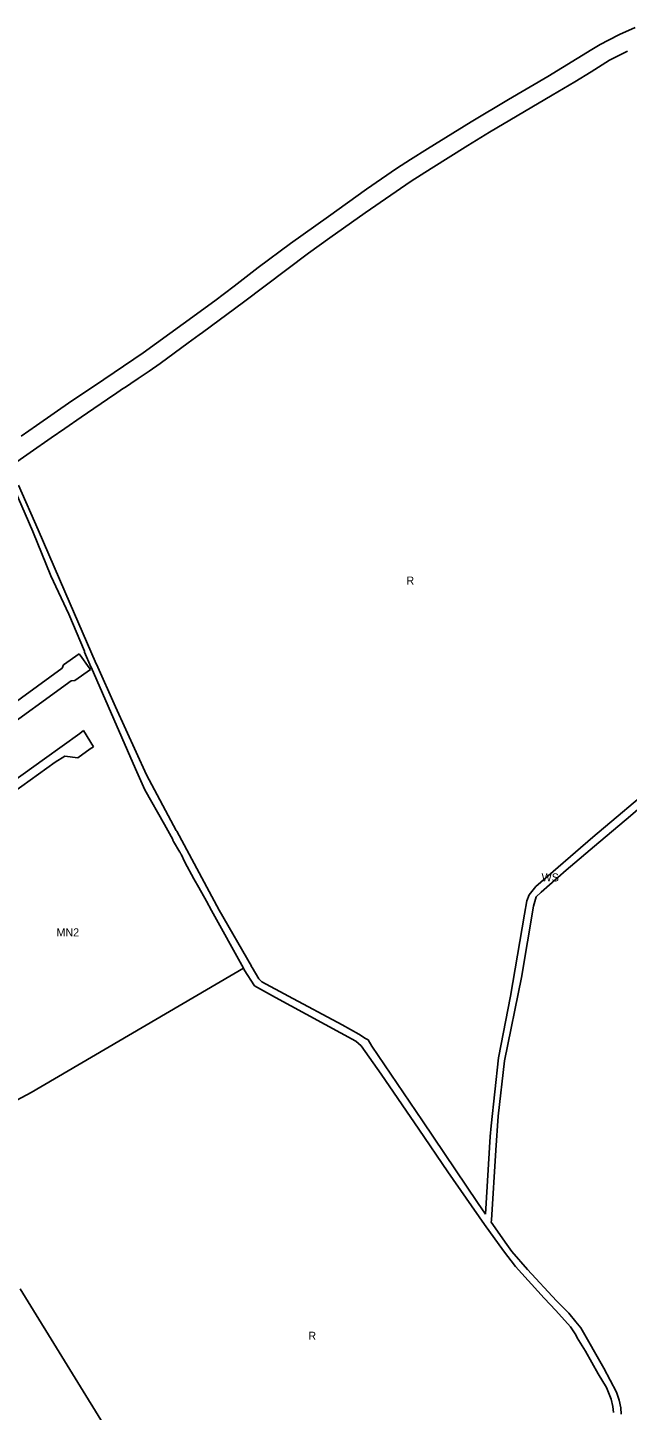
# Model space of a CAD drawing. Extents: x 7435758 to 7439981, y 5550649 to 5554049.
# Drawn here: x 7437849 to 7438238, y 5551345 to 5552243 of the extents above; entities that cross this region are included whole.
import ezdxf

# ---------------------------------------------------------------- set-up
doc = ezdxf.new("R2010")
doc.units = 0
doc.layers.add('linie_rozgraniczające', color=7, linetype='Continuous')
doc.layers.add('oznaczenia_przeznaczen', color=7, linetype='Continuous')

msp = doc.modelspace()

# ---------------------------------------------------------------- linework, layer by layer
at = {"layer": 'linie_rozgraniczające'}
for p, q in [((7438233.29, 5552238.74), (7438226.09, 5552235.07)), ((7438243.46, 5552243.15), (7438233.29, 5552238.74)), ((7438220.7, 5552232.29), (7438215.4, 5552228.93)), ((7438226.09, 5552235.07), (7438220.7, 5552232.29)), ((7438215.4, 5552228.93), (7438186.88, 5552211.52)), ((7438214.95, 5552214.44), (7438226.89, 5552222)), ((7438226.89, 5552222), (7438238.58, 5552227.97)), ((7438186.88, 5552211.52), (7438161.26, 5552196.44)), ((7438204.39, 5552207.89), (7438214.95, 5552214.44)), ((7438189.7, 5552199.25), (7438204.39, 5552207.89)), ((7438161.26, 5552196.44), (7438136.96, 5552182.06)), ((7438148.96, 5552175.27), (7438189.7, 5552199.25)), ((7438136.96, 5552182.06), (7438108.66, 5552164.34)), ((7438111.07, 5552151.69), (7438134.87, 5552166.6)), ((7438134.87, 5552166.6), (7438148.96, 5552175.27)), ((7438097.62, 5552157.42), (7438088.61, 5552151.62)), ((7438108.66, 5552164.34), (7438097.62, 5552157.42)), ((7438088.61, 5552151.62), (7438069.13, 5552138.13)), ((7438098, 5552143.5), (7438111.07, 5552151.69)), ((7438068.22, 5552122.79), (7438098, 5552143.5)), ((7438069.13, 5552138.13), (7438044.29, 5552120.56)), ((7438045.32, 5552106.59), (7438068.22, 5552122.79)), ((7438044.29, 5552120.56), (7438019.76, 5552103)), ((7438031.31, 5552096.54), (7438045.32, 5552106.59)), ((7437989.26, 5552064.78), (7438031.31, 5552096.54)), ((7438019.76, 5552103), (7437998.76, 5552087.24)), ((7437998.76, 5552087.24), (7437983.05, 5552075.14)), ((7437983.05, 5552075.14), (7437970.58, 5552065.72)), ((7437970.58, 5552065.72), (7437949.92, 5552050.67)), ((7437962.53, 5552045.04), (7437989.26, 5552064.78)), ((7437949.92, 5552050.67), (7437924.09, 5552031.87)), ((7437953.31, 5552038.3), (7437960.46, 5552043.5)), ((7437960.46, 5552043.51), (7437962.53, 5552045.04)), ((7437960.46, 5552043.5), (7437960.46, 5552043.51)), ((7437924.09, 5552031.87), (7437892.36, 5552010.52)), ((7437935.04, 5552024.99), (7437953.31, 5552038.3)), ((7437927.96, 5552020.01), (7437935.04, 5552024.99)), ((7437915.95, 5552011.93), (7437920.87, 5552015.23)), ((7437920.87, 5552015.23), (7437927.96, 5552020.01)), ((7437892.36, 5552010.52), (7437877.64, 5552000.61)), ((7437883.68, 5551990.07), (7437905.05, 5552004.59)), ((7437905.05, 5552004.59), (7437905.45, 5552004.86)), ((7437905.45, 5552004.86), (7437906.93, 5552005.82)), ((7437906.93, 5552005.82), (7437911.34, 5552008.83)), ((7437911.34, 5552008.83), (7437911.36, 5552008.84)), ((7437911.36, 5552008.84), (7437911.95, 5552009.24)), ((7437911.95, 5552009.24), (7437915.95, 5552011.93)), ((7437877.64, 5552000.61), (7437854.78, 5551984.69)), ((7437873.1, 5551982.72), (7437883.68, 5551990.07)), ((7437854.78, 5551984.69), (7437844.78, 5551977.68)), ((7437864.27, 5551976.69), (7437873.1, 5551982.72)), ((7437850.63, 5551967.13), (7437864.27, 5551976.69)), ((7437834.89, 5551956.1), (7437850.63, 5551967.13)), ((7437840.36, 5551943.66), (7437852.28, 5551915.86)), ((7437855.94, 5551916.89), (7437843.13, 5551945.94)), ((7437852.28, 5551915.86), (7437864.12, 5551887.06)), ((7437873.07, 5551876.82), (7437855.94, 5551916.89)), ((7437864.12, 5551887.06), (7437875.74, 5551862.03)), ((7437893.59, 5551829.8), (7437873.07, 5551876.82)), ((7437875.74, 5551862.03), (7437885.84, 5551837.94)), ((7437872.36, 5551829.12), (7437882.54, 5551836.36)), ((7437882.54, 5551836.36), (7437883.17, 5551835.49)), ((7437883.17, 5551835.49), (7437889.03, 5551827.25)), ((7437885.84, 5551837.94), (7437885.85, 5551837.43)), ((7437885.85, 5551837.43), (7437889.97, 5551827.94)), ((7437807.11, 5551780.31), (7437871.35, 5551826.92)), ((7437871.35, 5551826.92), (7437872.36, 5551829.12)), ((7437889.79, 5551826.18), (7437879.61, 5551818.93)), ((7437889.03, 5551827.25), (7437889.79, 5551826.18)), ((7437889.97, 5551827.94), (7437890.35, 5551827.58)), ((7437890.35, 5551827.58), (7437905.06, 5551793.87)), ((7437893.52, 5551829.77), (7437893.59, 5551829.8)), ((7437893.73, 5551829.5), (7437893.52, 5551829.77)), ((7437906.03, 5551801.93), (7437893.73, 5551829.5)), ((7437877.2, 5551818.71), (7437812.75, 5551772.12)), ((7437879.61, 5551818.93), (7437877.2, 5551818.71)), ((7437926.23, 5551757.79), (7437906.03, 5551801.93)), ((7437905.06, 5551793.87), (7437918.96, 5551761.62)), ((7437860.01, 5551768.18), (7437882.93, 5551784.61)), ((7437882.93, 5551784.61), (7437885.38, 5551786.59)), ((7437885.38, 5551786.59), (7437891.82, 5551775.94)), ((7437889.51, 5551774.56), (7437881.54, 5551768.85)), ((7437891.82, 5551775.94), (7437889.51, 5551774.56)), ((7438237.71, 5551728.66), (7438294.16, 5551777.35)), ((7437866.87, 5551766.02), (7437819.07, 5551731.54)), ((7437832.18, 5551748.17), (7437860.01, 5551768.18)), ((7437873.16, 5551769.78), (7437866.87, 5551766.02)), ((7437881.54, 5551768.85), (7437873.16, 5551769.78)), ((7438271.71, 5551764.41), (7438215.92, 5551717.18)), ((7437918.96, 5551761.62), (7437925.15, 5551748.04)), ((7437945.52, 5551721.51), (7437926.23, 5551757.79)), ((7437925.15, 5551748.04), (7437937.86, 5551725.48)), ((7438219.83, 5551713.75), (7438237.71, 5551728.66)), ((7437937.86, 5551725.48), (7437943.28, 5551715.71)), ((7437945.97, 5551721.06), (7437945.52, 5551721.51)), ((7437973.32, 5551669.86), (7437945.97, 5551721.06)), ((7438215.92, 5551717.18), (7438178.9, 5551685.08)), ((7437943.28, 5551715.71), (7437943.28, 5551715.19)), ((7437943.28, 5551715.19), (7437943.33, 5551715.23)), ((7437943.33, 5551715.23), (7437943.81, 5551714.42)), ((7437943.81, 5551714.42), (7437947.91, 5551707.42)), ((7438198.66, 5551695.84), (7438219.83, 5551713.75)), ((7437947.91, 5551707.42), (7437948.02, 5551707.38)), ((7437948.02, 5551707.38), (7437948.37, 5551706.64)), ((7437948.37, 5551706.64), (7437948.69, 5551706.09)), ((7437948.69, 5551706.09), (7437948.64, 5551706.06)), ((7437948.64, 5551706.06), (7437951.04, 5551700.99)), ((7437951.04, 5551700.99), (7437956.99, 5551690.23)), ((7437956.99, 5551690.23), (7437960.16, 5551684.51)), ((7438182.37, 5551681.54), (7438198.66, 5551695.84)), ((7437960.16, 5551684.51), (7437965.11, 5551675.57)), ((7438178.9, 5551685.08), (7438174.63, 5551679.7)), ((7438179.26, 5551678.36), (7438182.37, 5551681.54)), ((7437965.11, 5551675.57), (7437968.45, 5551669.53)), ((7438169.73, 5551625.93), (7438177.44, 5551672.46)), ((7438173.17, 5551675.87), (7438171.55, 5551667.19)), ((7438174.63, 5551679.7), (7438173.17, 5551675.87)), ((7438177.44, 5551672.46), (7438179.26, 5551678.36)), ((7437968.45, 5551669.53), (7437989.21, 5551632.03)), ((7437994.32, 5551633.42), (7437973.32, 5551669.86)), ((7438171.55, 5551667.19), (7438162.49, 5551613.97)), ((7437851.26, 5551551.21), (7437989.21, 5551632.03)), ((7437989.21, 5551632.03), (7437989.4, 5551631.69)), ((7437989.4, 5551631.69), (7437989.65, 5551631.23)), ((7437989.65, 5551631.23), (7437989.67, 5551631.09)), ((7437989.67, 5551631.09), (7437996.42, 5551620.51)), ((7437994.22, 5551633.38), (7437994.32, 5551633.42)), ((7437994.84, 5551632.59), (7437994.22, 5551633.38)), ((7437999.09, 5551625.26), (7437994.84, 5551632.59)), ((7437996.42, 5551620.51), (7438009.94, 5551612.97)), ((7438001.14, 5551623.17), (7437999.09, 5551625.26)), ((7438018.49, 5551613.81), (7438001.14, 5551623.17)), ((7438158.73, 5551571.9), (7438169.73, 5551625.93)), ((7438009.94, 5551612.97), (7438062.2, 5551584.7)), ((7438053.19, 5551595.29), (7438018.49, 5551613.81)), ((7438162.49, 5551613.97), (7438154.7, 5551573.89)), ((7438063.99, 5551589.12), (7438053.19, 5551595.29)), ((7438062.2, 5551584.7), (7438065.48, 5551581.68)), ((7438068.41, 5551586.43), (7438063.99, 5551589.12)), ((7438070.07, 5551585.42), (7438068.41, 5551586.43)), ((7438072.4, 5551581.37), (7438070.07, 5551585.42)), ((7438065.48, 5551581.68), (7438078.66, 5551563.27)), ((7438105.45, 5551532.88), (7438072.4, 5551581.37)), ((7438154.7, 5551573.89), (7438150.06, 5551529.61)), ((7438154.62, 5551535.84), (7438158.73, 5551571.9)), ((7438078.66, 5551563.27), (7438103.1, 5551527.46)), ((7437842.06, 5551546.41), (7437851.26, 5551551.21)), ((7438141.05, 5551479.77), (7438105.45, 5551532.88)), ((7438150.06, 5551529.61), (7438149.33, 5551522.61)), ((7438153.03, 5551513.93), (7438154.62, 5551535.84)), ((7438103.1, 5551527.46), (7438121.79, 5551499.8)), ((7438149.33, 5551522.61), (7438146.29, 5551472.31)), ((7438150.13, 5551468.46), (7438153.03, 5551513.93)), ((7438121.79, 5551499.8), (7438145.57, 5551465.54)), ((7438146.29, 5551472.31), (7438141.05, 5551479.77)), ((7438150.02, 5551467.01), (7438150.13, 5551468.46)), ((7438160.25, 5551452.47), (7438150.02, 5551467.01)), ((7438145.57, 5551465.54), (7438157.91, 5551448.48)), ((7438157.91, 5551448.48), (7438165.74, 5551438.23)), ((7438163.46, 5551447.98), (7438160.25, 5551452.47)), ((7438173.68, 5551436.25), (7438163.46, 5551447.98)), ((7438165.74, 5551438.23), (7438184.49, 5551417.75)), ((7438192.38, 5551415.96), (7438173.68, 5551436.25)), ((7437946.07, 5551258.39), (7437844.14, 5551423.82)), ((7438184.49, 5551417.75), (7438191.97, 5551409.72)), ((7438200.38, 5551407.94), (7438192.38, 5551415.96)), ((7438191.97, 5551409.72), (7438201.45, 5551399.06)), ((7438204.98, 5551402.3), (7438200.38, 5551407.94)), ((7438201.45, 5551399.06), (7438204.91, 5551393.83)), ((7438204.91, 5551393.83), (7438205.82, 5551391.94)), ((7438208.18, 5551398.33), (7438204.98, 5551402.3)), ((7438223.14, 5551372.26), (7438208.18, 5551398.33)), ((7438205.82, 5551391.94), (7438211.18, 5551383.22)), ((7438211.18, 5551383.22), (7438219.45, 5551368.6)), ((7438219.45, 5551368.6), (7438224.85, 5551359.55)), ((7438231.33, 5551356.57), (7438223.14, 5551372.26)), ((7438224.85, 5551359.55), (7438227.94, 5551352)), ((7438227.94, 5551352), (7438228.92, 5551347.4)), ((7438233.13, 5551351.35), (7438231.33, 5551356.57)), ((7438234.12, 5551346.36), (7438233.13, 5551351.35)), ((7438228.92, 5551347.4), (7438229.34, 5551343.38)), ((7438234.42, 5551342.4), (7438234.12, 5551346.36))]:
    msp.add_line(p, q, dxfattribs=at)

# ---------------------------------------------------------------- texts
at = {"layer": 'oznaczenia_przeznaczen'}
for s, p in [('R', (7438094.95, 5551881.32)), ('WS', (7438182.76, 5551688.45)), ('MN2', (7437867.77, 5551652.74)), ('R', (7438031.29, 5551390.67))]:
    msp.add_text(s, height=5.2, dxfattribs=at).set_placement(p)

doc.saveas('drawing.dxf')
